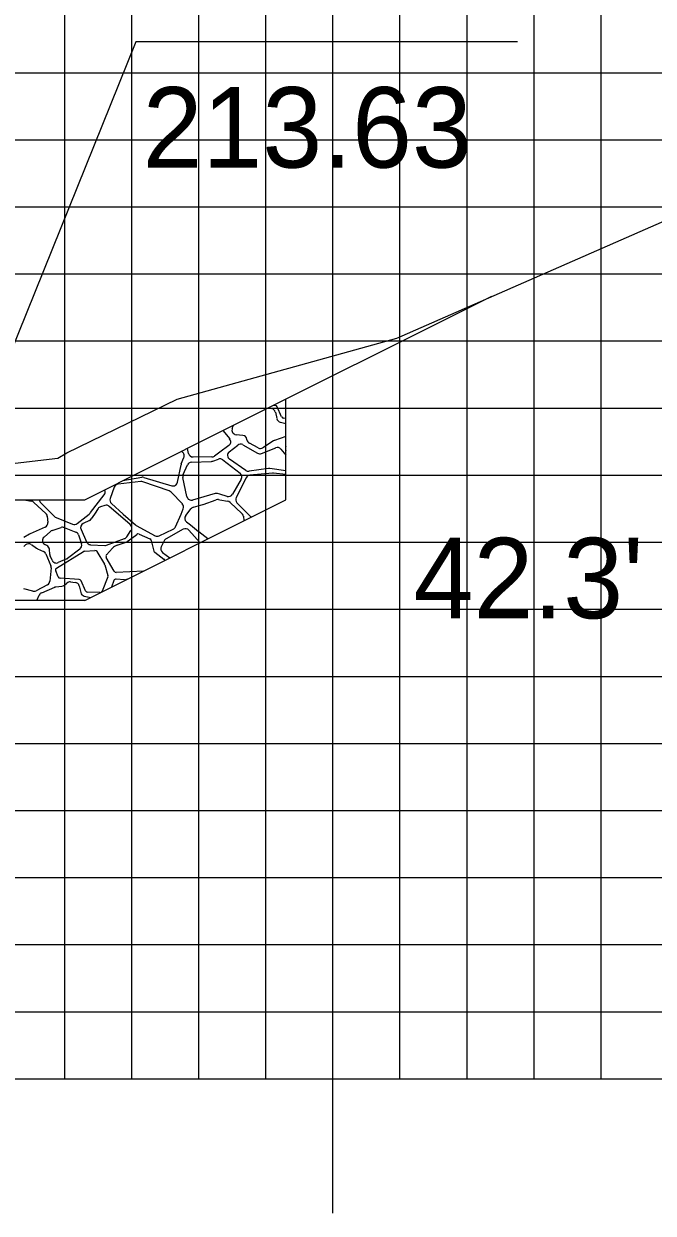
# Model space of a CAD drawing. Extents: x 851348 to 851692, y 364785 to 365005.
# Drawn here: x 851549.58 to 851558.97, y 364806.23 to 364823.96 of the extents above; entities that cross this region are included whole.
import ezdxf

# ---------------------------------------------------------------- set-up
doc = ezdxf.new("R2010")
doc.units = 0
for name, color, linetype in [('ANNOTATION', 7, 'Continuous'), ('D_Roadway_SubGrade', 7, 'Continuous'), ('D_Text_Standard', 7, 'Continuous'), ('MAJOR', 7, 'Continuous'), ('MINOR', 7, 'Continuous'), ('S_Roadway_Centerline', 7, 'Continuous')]:
    doc.layers.add(name, color=color, linetype=linetype)

msp = doc.modelspace()

# ---------------------------------------------------------------- linework, layer by layer
at = {"layer": 'ANNOTATION'}
for points in [[(851556.942, 364823.691), (851551.251, 364823.691), (851548.49, 364816.866)], [(851548.49, 364816.866), (851550.49, 364816.866), (851552.49, 364817.866), (851556.563, 364819.902)], [(851550.49, 364815.366), (851548.49, 364815.366)]]:
    msp.add_lwpolyline(points, dxfattribs=at)
at = {"layer": 'D_Roadway_SubGrade'}
for p, q in [((851553.22, 364818.231), (851553.272, 364818.225)), ((851553.331, 364818.271), (851553.303, 364818.272)), ((851553.426, 364818.1), (851553.36, 364818.25)), ((851553.332, 364818.172), (851553.354, 364818.075)), ((851553.49, 364818.079), (851553.456, 364818.08)), ((851552.55, 364817.896), (851552.651, 364817.773)), ((851552.69, 364817.932), (851552.709, 364817.975)), ((851553.407, 364818.022), (851553.49, 364818.005)), ((851552.645, 364817.579), (851552.771, 364817.681)), ((851552.848, 364817.826), (851552.746, 364817.836)), ((851552.848, 364817.687), (851553.066, 364817.561)), ((851552.909, 364817.761), (851552.909, 364817.766)), ((851553.078, 364817.638), (851552.945, 364817.709)), ((851553.307, 364817.744), (851553.147, 364817.641)), ((851553.49, 364817.81), (851553.321, 364817.751)), ((851552.038, 364817.555), (851552.02, 364817.63)), ((851552.383, 364817.504), (851552.104, 364817.503)), ((851552.505, 364817.576), (851552.424, 364817.517)), ((851552.639, 364817.674), (851552.505, 364817.576)), ((851553.126, 364817.556), (851553.337, 364817.639)), ((851553.414, 364817.62), (851553.49, 364817.531)), ((851551.874, 364817.127), (851551.926, 364817.386)), ((851551.93, 364817.399), (851551.969, 364817.495)), ((851551.955, 364817.24), (851552.02, 364817.384)), ((851552.079, 364817.425), (851552.382, 364817.438)), ((851552.402, 364817.442), (851552.485, 364817.471)), ((851552.55, 364817.461), (851552.806, 364817.263)), ((851552.892, 364817.302), (851552.649, 364817.469)), ((851553.229, 364817.331), (851552.94, 364817.291)), ((851553.49, 364817.295), (851553.248, 364817.331)), ((851551.06, 364817.151), (851551.341, 364817.201)), ((851551.372, 364817.199), (851551.787, 364817.074)), ((851552.014, 364816.912), (851551.951, 364817.197)), ((851552.823, 364817.175), (851552.691, 364816.948)), ((851552.896, 364817.193), (851552.747, 364816.901)), ((851553.292, 364817.264), (851552.951, 364817.23)), ((851553.49, 364817.243), (851553.306, 364817.264)), ((851550.791, 364817.006), (851550.788, 364817.015)), ((851550.93, 364817.053), (851550.869, 364816.884)), ((851551.327, 364817.137), (851550.987, 364817.098)), ((851551.749, 364816.998), (851551.357, 364817.133)), ((851551.945, 364816.803), (851551.776, 364816.98)), ((851549.58, 364816.865), (851549.697, 364816.845)), ((851549.732, 364816.827), (851549.909, 364816.662)), ((851549.835, 364816.821), (851550.003, 364816.653)), ((851550.49, 364815.366), (851553.49, 364816.866)), ((851550.576, 364816.674), (851550.781, 364816.939)), ((851550.888, 364816.81), (851551.064, 364816.653)), ((851552.434, 364816.957), (851552.099, 364816.861)), ((851552.112, 364816.756), (851552.253, 364816.795)), ((851552.258, 364816.797), (851552.451, 364816.865)), ((851552.505, 364816.947), (851552.471, 364816.957)), ((851552.485, 364816.868), (851552.505, 364816.865)), ((851552.613, 364816.916), (851552.505, 364816.947)), ((851552.505, 364816.865), (851552.621, 364816.845)), ((851552.656, 364816.827), (851552.834, 364816.662)), ((851552.76, 364816.821), (851552.928, 364816.653)), ((851549.931, 364816.619), (851549.939, 364816.527)), ((851550.003, 364816.653), (851550.04, 364816.617)), ((851550.375, 364816.511), (851550.553, 364816.653)), ((851550.553, 364816.653), (851550.564, 364816.662)), ((851550.634, 364816.653), (851550.584, 364816.58)), ((851550.689, 364816.734), (851550.634, 364816.653)), ((851550.791, 364816.781), (851550.726, 364816.761)), ((851550.987, 364816.653), (851550.856, 364816.767)), ((851551.168, 364816.495), (851550.987, 364816.653)), ((851551.064, 364816.653), (851551.245, 364816.491)), ((851551.843, 364816.461), (851551.926, 364816.653)), ((851551.926, 364816.653), (851551.958, 364816.729)), ((851551.995, 364816.63), (851552.014, 364816.653)), ((851552.014, 364816.653), (851552.076, 364816.733)), ((851552.855, 364816.619), (851552.861, 364816.551)), ((851552.928, 364816.653), (851552.964, 364816.617)), ((851549.899, 364816.458), (851549.675, 364816.359)), ((851550.002, 364816.407), (851550.136, 364816.452)), ((851550.062, 364816.602), (851550.307, 364816.501)), ((851550.182, 364816.451), (851550.356, 364816.384)), ((851550.558, 364816.557), (851550.466, 364816.511)), ((851551.258, 364816.482), (851551.538, 364816.329)), ((851552.067, 364816.486), (851552.006, 364816.534)), ((851552.187, 364816.389), (851552.067, 364816.486)), ((851549.668, 364816.355), (851549.58, 364816.303)), ((851549.882, 364816.31), (851549.978, 364816.394)), ((851550.396, 364816.342), (851550.441, 364816.208)), ((851550.434, 364816.423), (851550.516, 364816.237)), ((851550.814, 364816.188), (851551.083, 364816.286)), ((851551.116, 364816.312), (851551.179, 364816.406)), ((851551.138, 364816.254), (851551.265, 364816.349)), ((851551.299, 364816.353), (851551.462, 364816.281)), ((851551.6, 364816.327), (851551.809, 364816.427)), ((851551.959, 364816.425), (851551.704, 364816.285)), ((851552.209, 364816.225), (851552.043, 364816.41)), ((851552.327, 364816.284), (851552.189, 364816.387)), ((851549.58, 364816.169), (851549.608, 364816.193)), ((851549.693, 364816.198), (851549.771, 364816.142)), ((851549.784, 364816.136), (851549.873, 364816.096)), ((851549.926, 364816.182), (851549.896, 364816.198)), ((851549.969, 364816.051), (851549.962, 364816.128)), ((851550.07, 364815.848), (851550.469, 364816.092)), ((851550.418, 364816.131), (851550.233, 364815.992)), ((851550.484, 364816.097), (851550.64, 364816.11)), ((851550.575, 364816.196), (851550.787, 364816.184)), ((851550.672, 364816.093), (851550.784, 364815.904)), ((851550.814, 364816.047), (851550.902, 364816.143)), ((851550.972, 364816.188), (851551.092, 364816.23)), ((851551.482, 364816.258), (851551.52, 364816.101)), ((851551.676, 364816.255), (851551.631, 364816.166)), ((851549.909, 364816.06), (851549.982, 364815.882)), ((851550.003, 364815.964), (851549.974, 364816.03)), ((851550.22, 364815.984), (851550.093, 364815.928)), ((851550.929, 364815.799), (851550.81, 364816.007)), ((851551.533, 364816.082), (851551.668, 364815.982)), ((851551.651, 364816.081), (851551.758, 364816)), ((851549.987, 364815.849), (851549.969, 364815.654)), ((851550.094, 364815.716), (851550.057, 364815.805)), ((851550.787, 364815.896), (851550.835, 364815.738)), ((851551.366, 364815.803), (851550.96, 364815.782)), ((851549.933, 364815.599), (851549.763, 364815.509)), ((851549.848, 364815.48), (851550.041, 364815.56)), ((851550.058, 364815.565), (851550.15, 364815.577)), ((851550.406, 364815.679), (851550.123, 364815.695)), ((851550.186, 364815.592), (851550.224, 364815.624)), ((851550.275, 364815.64), (851550.348, 364815.633)), ((851550.407, 364815.58), (851550.429, 364815.483)), ((851550.502, 364815.508), (851550.436, 364815.658)), ((851550.834, 364815.715), (851550.75, 364815.503)), ((851550.924, 364815.661), (851550.887, 364815.564)), ((851551.08, 364815.671), (851550.959, 364815.682)), ((851551.127, 364815.684), (851551.096, 364815.673)), ((851549.713, 364815.503), (851549.58, 364815.538)), ((851549.777, 364815.366), (851549.811, 364815.444)), ((851550.482, 364815.43), (851550.579, 364815.41)), ((851550.717, 364815.482), (851550.532, 364815.488))]:
    msp.add_line(p, q, dxfattribs=at)
msp.add_lwpolyline([(851553.49, 364816.866), (851553.49, 364818.366)], dxfattribs=at)
for centre, radius, start, end in [((851553.265, 364818.157), 0.0684, 12.4074, 84.2894), ((851553.329, 364818.237), 0.0342, 23.7495, 86.6726), ((851553.42, 364818.089), 0.0684, 192.4074, 258.3664), ((851553.458, 364818.114), 0.0342, 203.7495, 268.1221), ((851552.753, 364817.904), 0.0684, 156.3179, 263.9458), ((851552.598, 364817.729), 0.0684, 306.2192, 39.4712), ((851552.814, 364817.628), 0.0684, 59.9314, 128.8845), ((851552.841, 364817.758), 0.0684, 6.8428, 83.9458), ((851552.977, 364817.769), 0.0684, 186.8428, 242.1524), ((851553.344, 364817.686), 0.0684, 109.406, 122.6806), ((851551.906, 364817.521), 0.0684, 337.4775, 70.3636), ((851552.104, 364817.572), 0.0684, 193.5819, 270.0888), ((851552.383, 364817.572), 0.0684, 270.0888, 306.2192), ((851552.688, 364817.526), 0.0684, 128.8845, 235.4375), ((851553.1, 364817.62), 0.0684, 239.9314, 291.541), ((851553.11, 364817.699), 0.0684, 242.1524, 302.6806), ((851553.362, 364817.576), 0.0684, 40.6013, 111.541), ((851553.55, 364817.631), 0.0684, 150.6134, 209.3866), ((851551.993, 364817.373), 0.0684, 157.4775, 168.7067), ((851552.082, 364817.357), 0.0684, 92.4366, 156.0375), ((851552.379, 364817.506), 0.0684, 272.4366, 289.44), ((851552.508, 364817.407), 0.0684, 92.6788, 109.44), ((851552.508, 364817.407), 0.0684, 52.3058, 92.6788), ((851553.238, 364817.263), 0.0684, 81.5289, 97.9435), ((851551.353, 364817.134), 0.0684, 73.267, 100.1543), ((851552.018, 364817.212), 0.0684, 156.0375, 192.4074), ((851552.764, 364817.209), 0.0684, 329.8265, 52.3058), ((851552.93, 364817.358), 0.0684, 235.4375, 277.9435), ((851552.957, 364817.162), 0.0684, 95.5993, 152.9691), ((851553.298, 364817.196), 0.0684, 83.5169, 95.5993), ((851550.727, 364816.981), 0.0684, 322.2243, 20.9245), ((851550.994, 364817.03), 0.0684, 96.5245, 160.0795), ((851551.334, 364817.069), 0.0684, 70.9362, 96.5245), ((851551.727, 364816.933), 0.0684, 43.5732, 70.9362), ((851551.807, 364817.14), 0.0684, 253.267, 348.7067), ((851549.685, 364816.777), 0.0684, 47.1211, 80.1342), ((851549.883, 364816.869), 0.0684, 183.1532, 225), ((851550.933, 364816.861), 0.0684, 160.0795, 228.2412), ((851551.895, 364816.756), 0.0684, 336.6444, 43.5732), ((851552.08, 364816.927), 0.0684, 192.4074, 285.9454), ((851552.235, 364816.861), 0.0684, 285.2551, 289.6538), ((851552.452, 364816.891), 0.0684, 74.0546, 105.9454), ((851552.474, 364816.801), 0.0684, 80.1342, 109.6538), ((851552.632, 364816.982), 0.0684, 254.0546, 329.8265), ((851552.61, 364816.777), 0.0684, 47.1211, 80.1342), ((851552.808, 364816.869), 0.0684, 152.9691, 225), ((851549.863, 364816.612), 0.0684, 36.5817, 47.1211), ((851549.863, 364816.612), 0.0684, 5.1944, 36.5817), ((851550.088, 364816.665), 0.0684, 225, 247.6938), ((851550.522, 364816.716), 0.0684, 308.6598, 322.2243), ((851550.746, 364816.696), 0.0684, 106.8584, 145.7843), ((851550.811, 364816.716), 0.0684, 48.8937, 106.8584), ((851552.049, 364816.588), 0.0684, 141.953, 231.3402), ((851552.13, 364816.69), 0.0684, 105.2551, 141.953), ((851552.787, 364816.612), 0.0684, 36.5817, 47.1211), ((851552.787, 364816.612), 0.0684, 5.1944, 36.5817), ((851553.013, 364816.665), 0.0684, 225, 236.3308), ((851549.871, 364816.521), 0.0684, 293.9625, 5.1944), ((851550.157, 364816.387), 0.0684, 69.0265, 108.4349), ((851550.333, 364816.564), 0.0684, 247.6938, 308.6598), ((851550.497, 364816.45), 0.0684, 116.5651, 203.7495), ((851550.528, 364816.618), 0.0684, 296.5651, 325.7843), ((851551.123, 364816.444), 0.0684, 326.0035, 48.8937), ((851551.291, 364816.542), 0.0684, 228.2412, 241.294), ((851551.78, 364816.488), 0.0684, 295.4039, 336.6444), ((851552.024, 364816.433), 0.0684, 50.9061, 51.3402), ((851549.703, 364816.297), 0.0684, 113.9625, 120.6507), ((851549.927, 364816.258), 0.0684, 131.1859, 242.3005), ((851550.023, 364816.342), 0.0684, 108.4349, 131.1859), ((851550.331, 364816.32), 0.0684, 18.7413, 69.0265), ((851551.059, 364816.35), 0.0684, 289.9256, 326.0035), ((851551.286, 364816.322), 0.0342, 66.1398, 126.7644), ((851551.448, 364816.25), 0.0342, 13.7608, 66.1398), ((851551.57, 364816.389), 0.0684, 241.294, 295.4039), ((851551.737, 364816.225), 0.0684, 118.7575, 153.4931), ((851551.992, 364816.365), 0.0684, 41.8334, 118.7575), ((851552.23, 364816.442), 0.0684, 230.9061, 233.4711), ((851549.653, 364816.142), 0.0684, 54.7824, 131.257), ((851549.811, 364816.198), 0.0684, 234.7824, 246.3706), ((851549.845, 364816.034), 0.0684, 22.4794, 66.3706), ((851549.894, 364816.121), 0.0684, 5.1944, 62.3005), ((851550.377, 364816.186), 0.0684, 307.0199, 18.7413), ((851550.487, 364816.063), 0.0342, 94.6669, 121.5514), ((851550.579, 364816.265), 0.0684, 203.7495, 266.7755), ((851550.643, 364816.076), 0.0342, 30.5102, 94.6669), ((851550.791, 364816.253), 0.0684, 266.7755, 289.9256), ((851551.028, 364816.027), 0.171, 109.1336, 137.3215), ((851551.036, 364816.391), 0.171, 289.1336, 306.7644), ((851551.553, 364816.109), 0.0342, 193.7608, 233.6864), ((851551.692, 364816.136), 0.0684, 153.4931, 232.6367), ((851550.037, 364816.057), 0.0684, 185.1944, 203.3852), ((851550.066, 364815.991), 0.0684, 203.3852, 293.8602), ((851550.192, 364816.046), 0.0684, 293.8602, 307.0199), ((851550.84, 364816.024), 0.0342, 137.3215, 209.792), ((851551.648, 364815.955), 0.0342, 11.3404, 53.6864), ((851549.919, 364815.856), 0.0684, 354.8056, 22.4794), ((851550.088, 364815.818), 0.0342, 121.5514, 202.6199), ((851550.755, 364815.886), 0.0342, 16.9275, 30.5102), ((851550.803, 364815.728), 0.0342, 338.1986, 16.9275), ((851550.958, 364815.816), 0.0342, 209.792, 272.9903), ((851549.901, 364815.66), 0.0684, 298.0725, 354.8056), ((851550.067, 364815.497), 0.0684, 97.125, 112.6199), ((851550.125, 364815.729), 0.0342, 202.6199, 266.6726), ((851550.141, 364815.644), 0.0684, 277.125, 310.3645), ((851550.268, 364815.572), 0.0684, 84.2894, 130.3645), ((851550.341, 364815.565), 0.0684, 12.4074, 84.2894), ((851550.404, 364815.644), 0.0342, 23.7495, 86.6726), ((851550.956, 364815.648), 0.0342, 84.4278, 159.0071), ((851551.084, 364815.705), 0.0342, 264.4278, 290.4835), ((851549.731, 364815.569), 0.0684, 255.2564, 298.0725), ((851549.874, 364815.417), 0.0684, 112.6199, 156.3179), ((851550.496, 364815.497), 0.0684, 192.4074, 258.3664), ((851550.533, 364815.522), 0.0342, 203.7495, 268.1221), ((851550.718, 364815.516), 0.0342, 268.1221, 277.6273), ((851550.718, 364815.516), 0.0342, 315.5028, 338.1986)]:
    msp.add_arc(centre, radius, start, end, dxfattribs=at)
at = {"layer": 'MAJOR'}
for p, q in [((851554.191, 364808.233), (851554.191, 364838.233)), ((851374.191, 364823.233), (851654.191, 364823.233)), ((851374.191, 364818.233), (851654.191, 364818.233)), ((851374.191, 364813.233), (851654.191, 364813.233)), ((851374.191, 364808.233), (851654.191, 364808.233)), ((851374.191, 364808.233), (851654.191, 364808.233)), ((851554.191, 364806.229), (851554.191, 364808.233))]:
    msp.add_line(p, q, dxfattribs=at)
at = {"layer": 'MINOR'}
for p, q in [((851550.191, 364808.233), (851550.191, 364838.233)), ((851551.191, 364808.233), (851551.191, 364838.233)), ((851552.191, 364808.233), (851552.191, 364838.233)), ((851553.191, 364808.233), (851553.191, 364838.233)), ((851555.191, 364808.233), (851555.191, 364838.233)), ((851556.191, 364808.233), (851556.191, 364838.233)), ((851557.191, 364808.233), (851557.191, 364838.233)), ((851558.191, 364808.233), (851558.191, 364838.233)), ((851374.191, 364822.233), (851654.191, 364822.233)), ((851374.191, 364821.233), (851654.191, 364821.233)), ((851374.191, 364820.233), (851654.191, 364820.233)), ((851374.191, 364819.233), (851654.191, 364819.233)), ((851374.191, 364817.233), (851654.191, 364817.233)), ((851374.191, 364816.233), (851654.191, 364816.233)), ((851374.191, 364815.233), (851654.191, 364815.233)), ((851374.191, 364814.233), (851654.191, 364814.233)), ((851374.191, 364812.233), (851654.191, 364812.233)), ((851374.191, 364811.233), (851654.191, 364811.233)), ((851374.191, 364810.233), (851654.191, 364810.233)), ((851374.191, 364809.233), (851654.191, 364809.233))]:
    msp.add_line(p, q, dxfattribs=at)
at = {"layer": 'S_Roadway_Centerline'}
msp.add_lwpolyline([(851528.153, 364821.217), (851532.695, 364821.183), (851534.614, 364821.155), (851534.741, 364821.138), (851535.856, 364820.75), (851536.504, 364820.632), (851539.427, 364819.92), (851541.118, 364819.528), (851541.299, 364819.5), (851543.429, 364818.558), (851543.759, 364818.774), (851544.424, 364818.506), (851544.854, 364818.171), (851545.494, 364817.569), (851545.801, 364817.315), (851546.992, 364817.226), (851547.458, 364817.185), (851548.519, 364817.304), (851550.09, 364817.488), (851550.223, 364817.565), (851551.866, 364818.366), (851555.144, 364819.274), (851560.825, 364821.765)], dxfattribs=at)

# ---------------------------------------------------------------- texts
at = {"layer": 'ANNOTATION'}
msp.add_text('213.63', height=1.2, dxfattribs=at).set_placement((851551.354, 364821.818))
at = {"layer": 'D_Text_Standard'}
msp.add_text("42.3'", height=1.2, dxfattribs=at).set_placement((851555.395, 364815.098))

doc.saveas('drawing.dxf')
